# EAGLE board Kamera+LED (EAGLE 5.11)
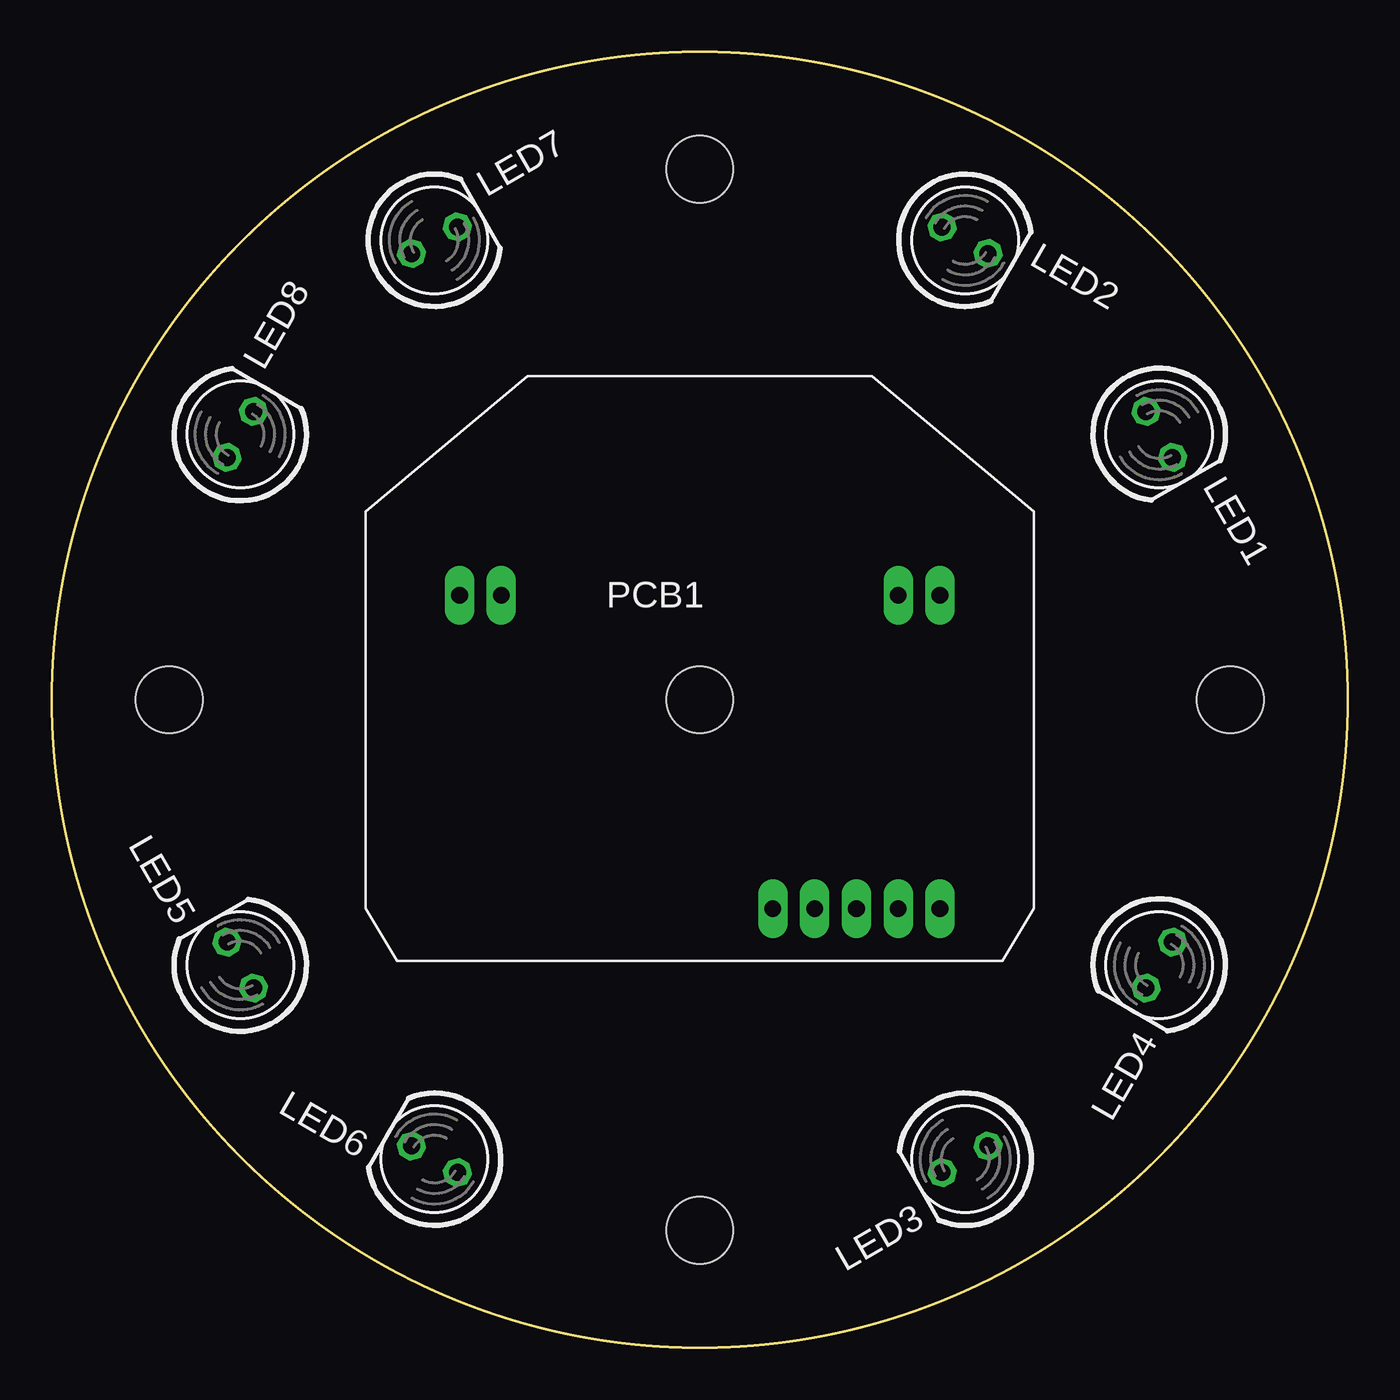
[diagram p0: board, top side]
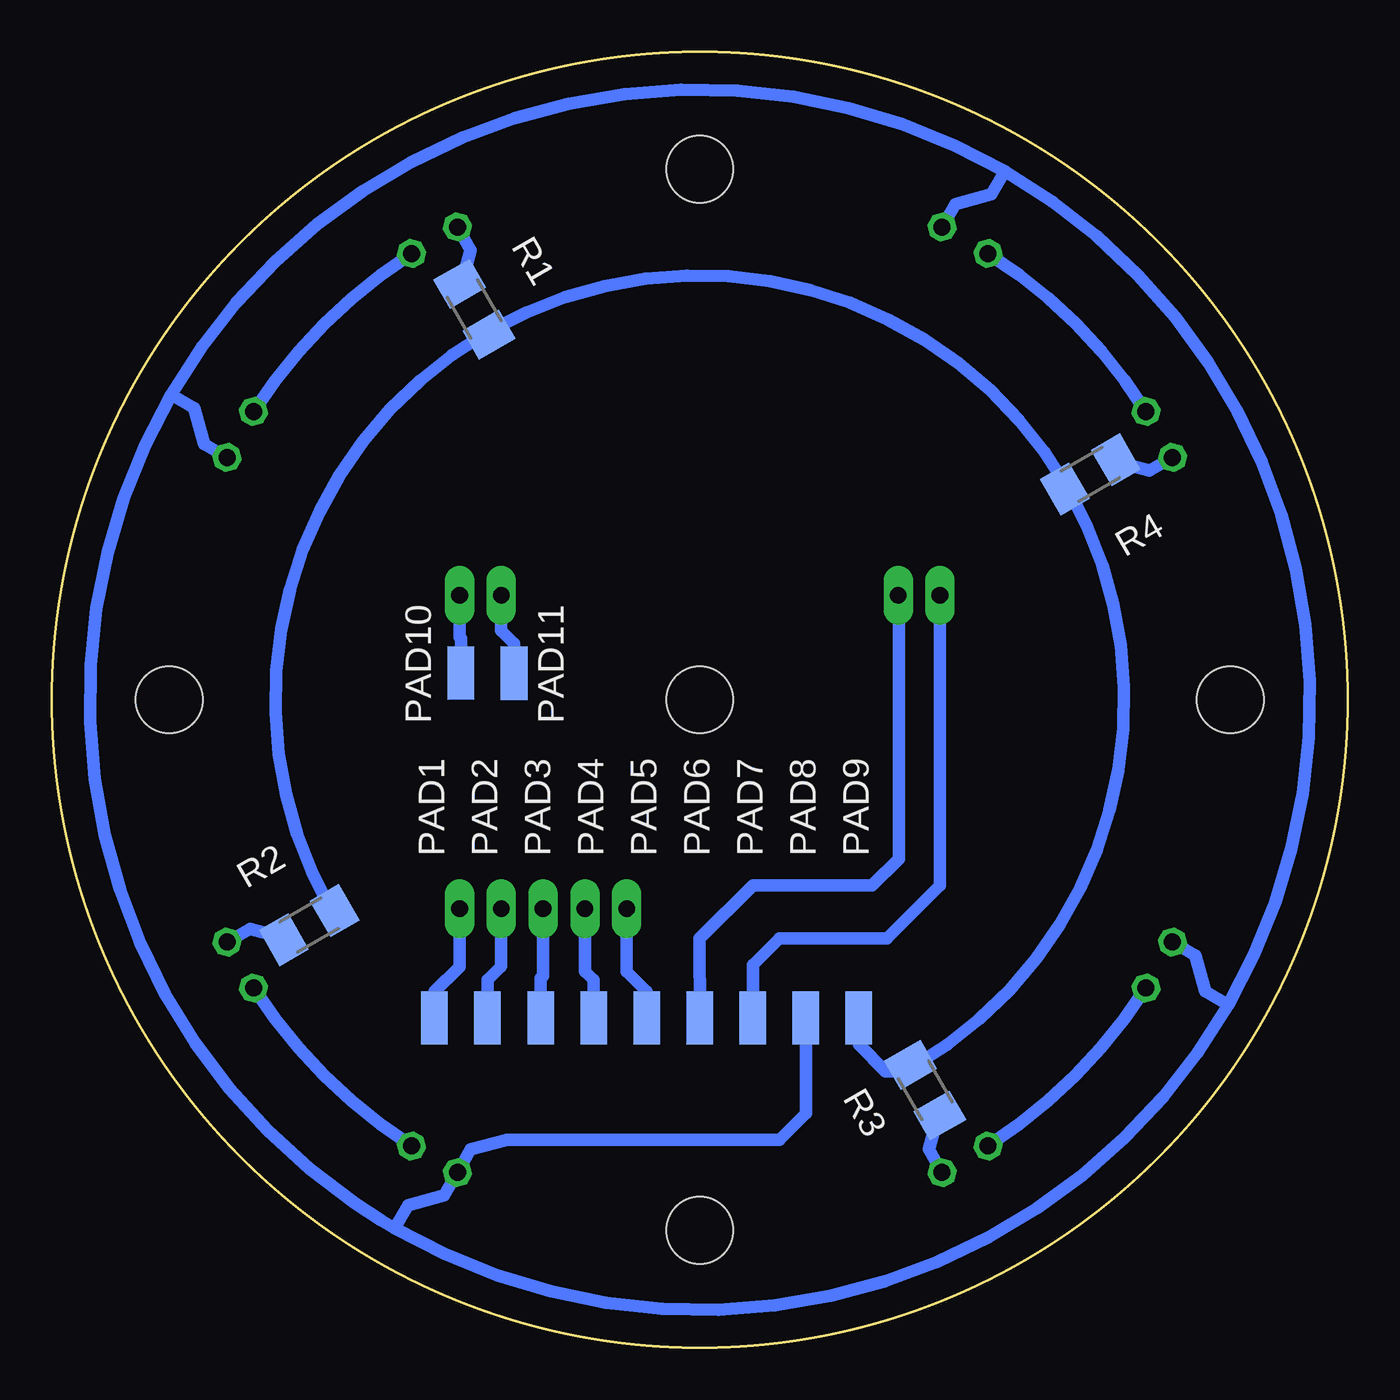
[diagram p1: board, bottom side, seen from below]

Size 62 x 62 mm. Coordinates in mm from the lower left corner, seen from the top.
Outline: circle at 31,31 radius 31
Copper layers (1*16): Top 0.035mm / dielectric 1.5mm / Bottom 0.035mm
Design rules "default": minimum track width 10mil, minimum drill 24mil, track to track 8mil, track to pad 8mil, pad to pad 8mil, via to via 8mil, smd to smd 8mil, copper to edge 40mil, drill to drill 8mil, minimum pad ring 10mil, minimum via ring 8mil, stop-mask expansion 4mil, vias tented up to drill 0mil, thermal gap 10mil
Holes 3.2 mm at 31,31 31,5.6 56.4,31 5.6,31 31,56.4

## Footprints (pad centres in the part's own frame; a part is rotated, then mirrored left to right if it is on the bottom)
LED5MM = drill 0.813 octagon: A -1.27,0; K 1.27,0
SMD1,27-2,54 = smd 1.27 x 2.54: 1 0,0
PCB_WEB_CAM = drill 0.8 pad 1.422 long: D+ 7.5,-10; D- 3.5,-10; GND 9.5,-10; MIC+ 9.5,5; MIC- 11.5,5; SHIELD 5.5,-10; SW1 -11.5,5; SW2 -9.5,5; V+ 11.5,-10
M1206 = smd 1.6 x 2: 1 -1.4,0; 2 1.4,0

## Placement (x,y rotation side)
LED1  W  [LED5MM]  53,43.7 300 top
LED2  W  [LED5MM]  43.7,53 330 top
LED3  W  [LED5MM]  43.7,9 210 top
LED4  W  [LED5MM]  53,18.3 240 top
LED5  W  [LED5MM]  9,18.3 120 top
LED6  W  [LED5MM]  18.3,9 150 top
LED7  W  [LED5MM]  18.3,53 30 top
LED8  W  [LED5MM]  9,43.7 60 top
PAD1  [SMD1,27-2,54]  43.7,15.76 0 bottom
PAD2  [SMD1,27-2,54]  41.16,15.76 0 bottom
PAD3  [SMD1,27-2,54]  38.62,15.76 0 bottom
PAD4  [SMD1,27-2,54]  36.08,15.76 0 bottom
PAD5  [SMD1,27-2,54]  33.54,15.76 0 bottom
PAD6  [SMD1,27-2,54]  31,15.76 0 bottom
PAD7  [SMD1,27-2,54]  28.46,15.76 0 bottom
PAD8  [SMD1,27-2,54]  25.92,15.76 0 bottom
PAD9  [SMD1,27-2,54]  23.38,15.76 0 bottom
PAD10  [SMD1,27-2,54]  42.43,32.27 0 bottom
PAD11  [SMD1,27-2,54]  39.89,32.27 0 bottom
PCB1  WEBCAM  [PCB_WEB_CAM]  31,31 0 top
R1  100  [M1206]  41.8,49.7 300 bottom
R2  100  [M1206]  49.7,20.2 30 bottom
R3  100  [M1206]  20.2,12.3 120 bottom
R4  100  [M1206]  12.3,41.8 210 bottom

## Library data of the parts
LED1-LED8 = led
PAD1-PAD11 = wirepad
PCB1 = PCB_Web_CAM_Logitech
R1-R4 = rcl

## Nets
N$1: LED2.A R1.1
N$2: LED1.A LED2.K
N$3: LED4.A R2.1
N$4: LED3.A LED4.K
N$5: LED6.A R3.1
N$6: LED5.A LED6.K
N$7: LED8.A R4.1
N$8: LED7.A LED8.K
N$9: LED1.K LED3.K LED5.K LED7.K PAD8.1
N$10: PAD6.1 PCB1.SW2
N$11: PAD7.1 PCB1.SW1
N$12: PAD1.1 PCB1.V+
N$13: PAD2.1 PCB1.GND
N$14: PAD9.1 R1.2 R2.2 R3.2 R4.2
N$15: PAD3.1 PCB1.D+
N$16: PAD5.1 PCB1.D-
N$17: PAD4.1 PCB1.SHIELD
N$18: PAD10.1 PCB1.MIC-
N$19: PAD11.1 PCB1.MIC+

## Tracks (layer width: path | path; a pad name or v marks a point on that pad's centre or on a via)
N$1
  Bottom 0.254: R1.1 42.43,51.32 42.3,51.28
  Bottom 0.61: LED2.A 41.97,52.53 42.3,51.28 42.43,50.8
N$2
  Bottom 0.61: LED1.A arc24 LED2.K
N$3
  Bottom 0.254: R2.1 51.32,19.57 51.28,19.7
  Bottom 0.61: LED4.A 52.53,20.04 51.28,19.7 50.8,19.57
N$4
  Bottom 0.61: LED3.A arc24 LED4.K
N$5
  Bottom 0.254: R3.1 19.57,10.68 19.7,10.71
  Bottom 0.61: LED6.A 20.04,9.47 19.7,10.71 19.57,11.2
N$6
  Bottom 0.61: LED5.A arc24 LED6.K
N$7
  Bottom 0.254: R4.1 10.68,42.43 10.71,42.3
  Bottom 0.61: LED8.A 9.47,41.97 10.71,42.3 11.2,42.43
N$8
  Bottom 0.61: LED8.K arc-26 LED7.A
N$9
  Bottom 0.254: 25.92,11.95 25.96,11.16 26,11.16 27.19,9.97 40.41,9.97 40.56,9.81 40.92,9.81 41.12,9.61 41.72,9.61 41.76,9.65 41.76,9.61 42.11,9.25 42.15,9.25 42.31,9.09 42.31,8.81 42.63,8.5 42.63,8.18 42.99,7.82 42.99,7.54 43.22,7.31 45.01,6.75 45.6,5.76 47.51,6.87 47.49,6.89 | 42.67,8.34 LED3.K 42.67,8.34
  Bottom 0.61: 56.3,45.61 55.2,44.97 54.73,43.23 LED1.K | 45.6,5.7 arc4 47.49,6.89 arc86 56.3,45.61 | 45.6,5.7 44.97,6.8 43.23,7.27 LED3.K 41.97,9.47 40.23,9.93 | 5.7,16.39 arc90 45.6,5.7 | LED5.K 7.27,18.77 6.8,17.03 5.7,16.39 | 5.7,16.39 arc-90 16.39,56.3 | LED7.K 18.77,54.73 17.03,55.2 16.39,56.3 | 16.39,56.3 arc-90 56.3,45.61 | PAD8.1 25.92,11.95 25.92,11.2 27.19,9.93 40.25,9.93
N$10
  Bottom 0.254: 23.38,22.11 22.82,22.11 21.48,23.38 PCB1.SW2
  Bottom 0.61: PAD6.1 31,19.57 28.46,22.11 23.38,22.11 | 23.38,22.11 22.75,22.11 21.48,23.38 21.48,36.02 | 23.38,22.11
N$11
  Bottom 0.254: 19.49,36.02 19.57,36.08 PCB1.SW1 | PAD7.1
  Bottom 0.61: 19.49,36.02 19.49,22.11 22.03,19.57 27.19,19.57 28.46,18.3 PAD7.1 | PAD7.1 | PAD7.1 | PAD7.1
N$12
  Bottom 0.254: 42.51,18.22 42.43,18.3 42.5,18.25
  Bottom 0.61: 42.5,18.25 PCB1.V+ | PAD1.1 43.7,17.03 42.51,18.22
N$13
  Bottom 0.254: 41.16,17.03 41.16,17.55 41.16,17.59 40.56,18.18 40.56,18.22 PCB1.GND
  Bottom 0.61: PCB1.GND 40.5,18.25 | PAD2.1 41.16,17.03 | 41.16,17.03 | 41.16,17.03 41.16,17.59 40.52,18.22
N$14
  Bottom 0.254: 20.84,13.22 R3.2 20.84,13.22 | 20.84,13.22 | 20.84,13.22 20.84,13.4 | 41.08,48.64 41.16,48.78 R1.2 | R4.2 13.22,41.16 13.36,41.08 | R2.2 48.78,20.84 48.64,20.92
  Bottom 0.61: 48.6,20.84 arc0 48.64,20.92 arc90 41.16,48.6 arc0 41.08,48.64 arc90 13.4,41.16 arc0 13.36,41.08 arc90 20.84,13.4 | PAD9.1 23.38,14.49 22.11,13.22 20.84,13.22 | 20.84,13.22
N$15
  Bottom 0.254: 38.62,17.03 38.62,18.3 38.5,18.3
  Bottom 0.61: 38.5,17.79 38.5,18.3 PCB1.D+ | PAD3.1 38.62,17.03 | 38.62,17.03 | 38.62,17.03 38.62,17.66 38.5,17.78
N$16
  Bottom 0.254: 33.54,17.03 34.49,17.98 PCB1.D-
  Bottom 0.61: PAD5.1 33.54,17.03 | 33.54,17.03 | 33.54,17.03 34.49,17.98 | PCB1.D- 34.5,18
N$17
  Bottom 0.254: 36.08,17.03 36.08,17.62 36.52,18.06 PCB1.SHIELD
  Bottom 0.61: PCB1.SHIELD 36.5,18 | PAD4.1 36.08,17.03 36.08,17.59 36.48,17.98
N$18
  Bottom 0.254: PAD10.1 42.43,33.54 42.43,34.81 PCB1.MIC-
  Bottom 0.61: 42.43,33.54 PAD10.1 | 42.43,33.54 | 42.43,33.54 | 42.43,33.54 42.43,33.94 42.51,34.02 | PCB1.MIC- 42.5,34
N$19
  Bottom 0.254: 39.89,33.54 40.48,34.33 PCB1.MIC+ | PAD11.1
  Bottom 0.61: PAD11.1 | PAD11.1 39.89,33.54 | 39.89,33.54 | 39.89,33.54 39.89,33.7 40.49,34.29 | PCB1.MIC+ 40.5,34.31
